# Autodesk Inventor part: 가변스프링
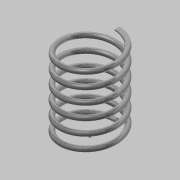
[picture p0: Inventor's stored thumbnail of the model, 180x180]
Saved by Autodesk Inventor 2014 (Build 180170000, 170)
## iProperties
Created: 2016-06
Part Number: 가변스프링
Material: 스테인레스 스틸
Document SubType Name: Modeling
Designer: user
Density: 8.08 g/cm^3
Appearance: 반연마
Mass: 85.0382 g
Surface Area: 106.449 cm^2
Volume: 10.5245 cm^3
Author: user
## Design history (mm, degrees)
sketch "스케치1"
  geometry: 1 further point
sketch "스케치2"
  geometry: L1 (0, 0)-(22.5, 0); L2 (22.5, 0)-(22.5, 67.25); L3 (22.5, 67.25)-(0, 67.25); L4 (0, 67.25)-(0, 0); C1 r 2 at (22.5, 0)
  constraints: 8 end point, 2 parallel, 1 centre point, 1 coincident, 1 horizontal, 1 perpendicular
  dimensions: "d0" = 45 diameter of L2 L4; "d1" = 67.25 distance between parallel lines of L1 L3 (derived); "d2" = 4 diameter of C1
feature "코일1" sketch "스케치2" pitch "d3" = 10; turns "d5" = 6; dims "d4" = 67.25 (= d1), "d6" = 0, angle "d7" = 90 deg, angle "d8" = 90 deg, "d9" = 0, "d10" = 0
sketch "스케치3"
  geometry: L1 (0, 24.5)-(0, 20.5) reference; 1 further point
  constraints: 1 vertical alignment
extrude "돌출1" cut sketch "스케치3" stored distance "d11" = 10; taper "d12" = 0 deg
node "작업 평면1"
sketch "스케치4"
  geometry: L1 (0, 2)-(0, -2) reference; 2 further points
  constraints: 1 other
extrude "돌출2" cut sketch "스케치4" stored distance "d13" = 10; taper "d14" = 0 deg
node "솔리드1"
node "절단 모서리 투영1"
node "절단 모서리 투영2"
